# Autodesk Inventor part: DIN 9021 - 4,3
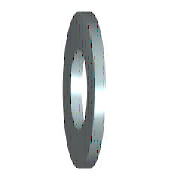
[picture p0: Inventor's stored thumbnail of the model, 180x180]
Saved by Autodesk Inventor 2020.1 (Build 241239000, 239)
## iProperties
Created: 2019-01
Part Number: DIN 9021 - 4,3
Material: Stahl, weich
Description: Unterlegscheibe
Document SubType Name: Modeling
Standard: DIN 9021
Designer: lutzd
Standards Organization: DIN
Language: de-DE
Size Designation: 4,3
Categories: <MemberInstance><Categories><Category DisplayName="Verbindungselemente" InternalName="e4da775c-781d-43d5-af7c-5136215cf5a6" Mnemonic="FSTN"><Category DisplayNam
Mass: 0.773816 g
Surface Area: 2.48359 cm^2
Volume: 0.0985753 cm^3
Density: 7.85 g/cm^3
Appearance: Halbpoliert
IsCustomPart: 0
Author: lutzd
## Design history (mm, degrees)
workaxis "Work Axis1"
workplane "Work Plane1"
body "Solid1"
sketch "Skizze"
  geometry: C1 r 6 at (0, 0); C2 r 2.15 at (0, 0); 1 further point
  constraints: 2 centre point, 2 coincident
  dimensions: "d0" = 4.3 diameter of C2 (= SD1); "d1" = 12 diameter of C1 (= SD2)
extrude "Körper" new body sketch "Skizze" distance "d2" = 1 (= SD); taper "d3" = 0 deg
other parameters: "SD1" = 4.3 [user parameter; used in 1 equation term], "SD2" = 12 [user parameter; used in 1 equation term], "SD" = 1 [user parameter; used in 1 equation term], "d4" = 0, "d5" = 0, "d6" = 0, "d7" = 0, "NND" = 4 [user parameter]
